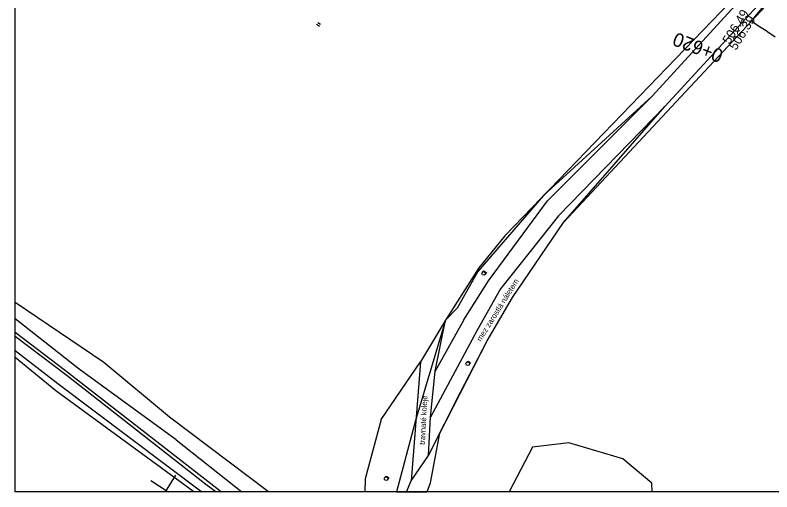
# Model space of a CAD drawing. Extents: x -636600 to -628587, y -1090963 to -1085869.
# Drawn here: x -629847.3 to -629681.7, y -1090224.9 to -1090120.7 of the extents above; entities that cross this region are included whole.
import ezdxf

# ---------------------------------------------------------------- set-up
doc = ezdxf.new("R2010")
doc.units = 0
for name, color, linetype in [('01_PARCELY_NÁVRH_PC', 7, 'Continuous'), ('08_LEGENDA_HV', 7, 'Continuous'), ('15', 7, 'Continuous'), ('22', 7, 'Continuous'), ('40', 7, 'Continuous'), ('42', 7, 'Continuous'), ('43', 7, 'Continuous'), ('60', 7, 'Continuous'), ('Ex_Minor Contours', 7, 'Continuous'), ('HEKTOMETRY20', 7, 'Continuous'), ('koty_vše', 7, 'Continuous'), ('síť křížků', 7, 'Continuous')]:
    doc.layers.add(name, color=color, linetype=linetype)

msp = doc.modelspace()

# ---------------------------------------------------------------- linework, layer by layer
at = {"layer": '01_PARCELY_NÁVRH_PC'}
msp.add_line((-629763.83, -1090224.9), (-629757.08, -1090224.9), dxfattribs=at)
for points in [[(-629590.44, -1089927.9), (-629610.34, -1089962.86), (-629611.05, -1089962.47), (-629613.94, -1089967.55), (-629651.31, -1090060.76), (-629656.7, -1090071.62), (-629663.92, -1090084.26), (-629669.51, -1090092.1), (-629671.7, -1090096.43), (-629679.1, -1090105.56), (-629740.1, -1090168.89), (-629745.82, -1090175.94), (-629753.08, -1090187.33), (-629759.69, -1090209.29), (-629763.83, -1090224.9)], [(-629757.08, -1090224.9), (-629756.4, -1090222.95), (-629754.36, -1090212.07), (-629743.98, -1090191.89), (-629738.43, -1090182.38), (-629727.31, -1090166.03), (-629671.82, -1090106.56), (-629662.5, -1090094.94), (-629652.06, -1090078.29), (-629645.47, -1090064.84), (-629624.55, -1090013.22), (-629617.14, -1089992.88), (-629607.22, -1089968.87), (-629597.44, -1089950.1), (-629584.51, -1089927.9)]]:
    msp.add_lwpolyline(points, dxfattribs=at)
at = {"layer": '08_LEGENDA_HV'}
for p, q in [((-629847.27, -1090224.9), (-629847.27, -1089927.9)), ((-629007.27, -1090224.9), (-629847.27, -1090224.9))]:
    msp.add_line(p, q, dxfattribs=at)
at = {"layer": '22'}
for p, q in [((-629833.27, -1090198.09), (-629847.27, -1090187.05)), ((-629847.27, -1090194), (-629837.95, -1090201.2)), ((-629812.05, -1090213.51), (-629833.27, -1090198.09)), ((-629837.95, -1090201.2), (-629806.4, -1090224.9)), ((-629812.05, -1090213.51), (-629797.7, -1090224.9))]:
    msp.add_line(p, q, dxfattribs=at)
at = {"layer": '40'}
for p, q in [((-629755.37, -1090198.53), (-629753.08, -1090187.33)), ((-629758.54, -1090196.48), (-629760.62, -1090222.46)), ((-629756.39, -1090208.6), (-629755.37, -1090198.53)), ((-629756.83, -1090216.96), (-629756.39, -1090208.6))]:
    msp.add_line(p, q, dxfattribs=at)
at = {"layer": '42'}
for p, q in [((-629707.87, -1090138.35), (-629674.34, -1090101.71)), ((-629705.08, -1090140.65), (-629671.28, -1090103.86)), ((-629707.87, -1090138.35), (-629731.64, -1090160.12)), ((-629727.31, -1090166.03), (-629705.08, -1090140.65)), ((-629731.64, -1090160.12), (-629746.04, -1090176.72)), ((-629738.43, -1090182.38), (-629727.31, -1090166.03)), ((-629746.04, -1090176.72), (-629750.54, -1090184.71)), ((-629743.98, -1090191.89), (-629738.43, -1090182.38)), ((-629827.86, -1090196.58), (-629847.27, -1090183.49)), ((-629750.54, -1090184.71), (-629753.08, -1090187.33)), ((-629753.08, -1090187.33), (-629758.54, -1090196.48)), ((-629749.84, -1090203.11), (-629743.98, -1090191.89)), ((-629838.36, -1090202.78), (-629847.27, -1090195.52)), ((-629813.46, -1090208.57), (-629827.86, -1090196.58)), ((-629767.17, -1090209.08), (-629758.54, -1090196.48)), ((-629808.19, -1090224.9), (-629838.36, -1090202.78)), ((-629756.83, -1090216.96), (-629749.84, -1090203.11)), ((-629791.83, -1090224.9), (-629813.46, -1090208.57)), ((-629767.17, -1090209.08), (-629770.68, -1090222.07)), ((-629734.08, -1090215.09), (-629739.16, -1090224.9)), ((-629726.12, -1090214.17), (-629734.08, -1090215.09)), ((-629714.28, -1090217.71), (-629726.12, -1090214.17)), ((-629760.62, -1090222.46), (-629756.83, -1090216.96)), ((-629707.94, -1090223.02), (-629714.28, -1090217.71)), ((-629770.68, -1090222.07), (-629770.73, -1090224.9)), ((-629761.63, -1090224.9), (-629760.62, -1090222.46)), ((-629707.9, -1090224.9), (-629707.94, -1090223.02))]:
    msp.add_line(p, q, dxfattribs=at)
at = {"layer": '43'}
for p, q in [((-629780.69, -1090123.13), (-629781.32, -1090122.73)), ((-629780.42, -1090122.71), (-629781.05, -1090122.31)), ((-629744.41, -1090177.37), (-629744.36, -1090177.28)), ((-629744.36, -1090177.28), (-629744.09, -1090176.86)), ((-629747.89, -1090197.09), (-629747.83, -1090197.01)), ((-629747.83, -1090197.01), (-629747.57, -1090196.59)), ((-629765.76, -1090222.25), (-629765.71, -1090222.16)), ((-629765.71, -1090222.16), (-629765.44, -1090221.74))]:
    msp.add_line(p, q, dxfattribs=at)
for centre in [(-629744.75, -1090177.15), (-629748.23, -1090196.88), (-629766.1, -1090222.03)]:
    msp.add_circle(centre, 0.4, dxfattribs=at)
for centre in [(-629744.7, -1090177.07), (-629748.17, -1090196.8), (-629766.05, -1090221.95)]:
    msp.add_arc(centre, 0.4, 317.5323, 155.0179, dxfattribs=at)
at = {"layer": '60'}
for p, q in [((-629730.79, -1090161.24), (-629707.87, -1090138.35)), ((-629728.36, -1090164.54), (-629705.08, -1090140.65)), ((-629743.71, -1090178.72), (-629730.79, -1090161.24)), ((-629728.36, -1090164.54), (-629741.04, -1090180.47)), ((-629749.1, -1090187.27), (-629743.71, -1090178.72)), ((-629741.04, -1090180.47), (-629746.26, -1090189.72)), ((-629749.1, -1090187.27), (-629755.37, -1090198.53)), ((-629847.27, -1090189.96), (-629836.23, -1090198.35)), ((-629746.26, -1090189.72), (-629756.39, -1090208.6)), ((-629835.91, -1090199.54), (-629847.27, -1090190.95)), ((-629836.23, -1090198.35), (-629805.08, -1090222.54)), ((-629805.54, -1090223.26), (-629835.91, -1090199.54)), ((-629803.38, -1090224.9), (-629805.54, -1090223.26)), ((-629805.08, -1090222.54), (-629802.12, -1090224.9))]:
    msp.add_line(p, q, dxfattribs=at)
at = {"layer": 'Ex_Minor Contours'}
msp.add_lwpolyline([(-629680.94, -1090125.5), (-629682.58, -1090124.35), (-629682.93, -1090124.11), (-629683.29, -1090123.87), (-629683.65, -1090123.64), (-629684.02, -1090123.41), (-629685.49, -1090122.51), (-629685.78, -1090122.27), (-629685.9, -1090122.01), (-629685.87, -1090121.72), (-629685.68, -1090121.4), (-629681.97, -1090116.87), (-629681.85, -1090116.71), (-629681.74, -1090116.55), (-629681.64, -1090116.38)], dxfattribs=at)
at = {"layer": 'síť křížků'}
for p, q in [((-629814.38, -1090224.9), (-629812.09, -1090221.25)), ((-629814.22, -1090224.64), (-629817.61, -1090222.51)), ((-629814.22, -1090224.64), (-629813.81, -1090224.9))]:
    msp.add_line(p, q, dxfattribs=at)

# ---------------------------------------------------------------- texts
at = {"layer": '15'}
for s, rotation, p in [('mez zarostlá náletem', 57.8371, (-629745.38, -1090192.11)), ('travnaté koleje', 87.0047, (-629757.62, -1090214.62))]:
    msp.add_text(s, height=1.2, rotation=rotation, dxfattribs=at).set_placement(p)
at = {"layer": 'HEKTOMETRY20'}
msp.add_text('0+620', height=3, rotation=158.8616, dxfattribs=at).set_placement((-629692.1, -1090128.39))
at = {"layer": 'koty_vše'}
for s, p in [('506.49', (-629690.98, -1090127.18)), ('506.39', (-629689.54, -1090128.49))]:
    msp.add_text(s, height=2, rotation=57.8371, dxfattribs=at).set_placement(p)

doc.saveas('drawing.dxf')
